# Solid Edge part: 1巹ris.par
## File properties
Author: Egon 815
Template: Normal.par
Last saved by: Egon 815
Revision: 5
Application: Solid Edge
Accuracy: 0,990
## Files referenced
..\Laev.asm
.C:\Kool\3D Modelleerimine\LaevaJoonis\Laev.asm
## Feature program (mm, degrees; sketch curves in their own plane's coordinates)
swept protrusion "unnamed SweptProtrusion 1"
sketch for "ExtrudedCutout_2" plane through (0, 0, 0) normal (0, -1, 0) x-axis (1, 0, 0)
  line (0, 7039.6525) -> (0, 4324.8507)
  line (0, 4324.8507) -> (-842.5239, 4324.8507)
  line (-842.5239, 4324.8507) -> (-842.5239, 7039.6525)
  line (-842.5239, 7039.6525) -> (0, 7039.6525)
extrude "ExtrudedCutout_2" cut finite symmetric
sketch for "unnamed Protrusion 1" plane through (11297.2682, -58110, 5032.5774) normal (-0.153386, -0.988166, 0) x-axis (0.988166, -0.153386, 0)
  line (0, 0) -> (0, 1000)
  line (0, 1000) -> (-60, 1000)
  line (-60, 1000) -> (-60, 0)
  line (0, 0) -> (-60, 0)
extrude "unnamed Protrusion 1" add to key point along +normal
sketch for "ExtrudedCutout_23" plane through (0, 0, 0) normal (1, 0, 0) x-axis (0, 1, 0)
  line (107824.8443, 5532.5774) -> (107824.8443, 5032.5774)
  line (107824.8443, 5032.5774) -> (108824.8443, 5032.5774)
  line (108824.8443, 5032.5774) -> (108824.8443, 5532.5774)
  line (108824.8443, 5532.5774) -> (107824.8443, 5532.5774)
extrude "ExtrudedCutout_23" cut finite along +normal
extrude "unnamed Cutout 1" cut finite
extrude "unnamed Cutout 2" cut finite
extrude "unnamed Cutout 3" cut finite
extrude "unnamed Cutout 4" cut finite
extrude "unnamed Cutout 5" cut finite
extrude "unnamed Cutout 6" cut finite
extrude "unnamed Cutout 7" cut finite
extrude "unnamed Cutout 8" cut finite
extrude "unnamed Cutout 9" cut finite
extrude "unnamed Cutout 10" cut finite
extrude "unnamed Cutout 11" cut finite
extrude "unnamed Cutout 12" cut finite
extrude "unnamed Cutout 13" cut finite
extrude "unnamed Cutout 14" cut finite
extrude "unnamed Cutout 15" cut finite
extrude "unnamed Cutout 16" cut finite
extrude "unnamed Cutout 17" cut finite
extrude "unnamed Cutout 18" cut finite
extrude "unnamed Cutout 19" cut finite
extrude "unnamed Cutout 20" cut finite
extrude "unnamed Cutout 21" cut finite
extrude "unnamed Cutout 22" cut finite
extrude "unnamed Cutout 23" cut finite
extrude "unnamed Cutout 24" cut finite
extrude "unnamed Cutout 25" cut finite
extrude "unnamed Cutout 26" cut finite
extrude "unnamed Cutout 27" cut finite
extrude "unnamed Cutout 28" cut finite
extrude "unnamed Cutout 29" cut finite
extrude "unnamed Cutout 30" cut finite
extrude "unnamed Cutout 31" cut finite
extrude "unnamed Cutout 32" cut finite
extrude "unnamed Cutout 33" cut finite
extrude "unnamed Cutout 34" cut finite
extrude "unnamed Cutout 35" cut finite
extrude "unnamed Cutout 36" cut finite
extrude "unnamed Cutout 37" cut finite
extrude "unnamed Cutout 38" cut finite
extrude "unnamed Cutout 39" cut finite
body pattern "unnamed BodyPattern 1"
pattern "unnamed Pattern 1"
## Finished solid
Body 1: solid body, 314 faces, 936 edges, 624 vertices.
  Faces by surface: plane 304, spline 10
  Edges by curve: line 516, intersection 256, spline 164
Bounding box of the edges (mm; curved faces can reach further): 33639.205 x 170025.692 x 1000.000, from (-16819.6027, -59033.4604, 5032.5774) to (16819.6027, 110992.2321, 6032.5774).
Planar faces by outward normal: +y 2, +z 1, -y 2, -z 149, oblique 150
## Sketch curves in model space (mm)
line (0, 108824.8443, 5032.5774) -> (0, 108824.8443, 5532.5774)
line (0, 108824.8443, 5532.5774) -> (0, 107824.8443, 5532.5774)
line (0, 107824.8443, 5532.5774) -> (0, 107824.8443, 5032.5774)
line (0, 107824.8443, 5032.5774) -> (0, 108824.8443, 5032.5774)
line (11324.5713, -58114.2381, 5532.5774) -> (11324.5713, -58114.2381, 5027.0031)
line (11324.5713, -58114.2381, 5027.0031) -> (11204.1478, -58095.5456, 5027.0031)
line (11204.1478, -58095.5456, 5027.0031) -> (11204.1478, -58095.5456, 5532.5774)
line (11204.1478, -58095.5456, 5532.5774) -> (11324.5713, -58114.2381, 5532.5774)
line (0, 0, 4324.8507) -> (-842.5239, 0, 4324.8507)
line (-842.5239, 0, 4324.8507) -> (-842.5239, 0, 7039.6525)
line (-842.5239, 0, 7039.6525) -> (0, 0, 7039.6525)
line (0, 0, 7039.6525) -> (0, 0, 4324.8507)
line (11297.2682, -58110, 6032.5774) -> (11237.9782, -58100.7968, 6032.5774)
line (11237.9782, -58100.7968, 6032.5774) -> (11237.9782, -58100.7968, 5032.5774)
line (11297.2682, -58110, 5032.5774) -> (11237.9782, -58100.7968, 5032.5774)
line (11297.2682, -58110, 5032.5774) -> (11297.2682, -58110, 6032.5774)
arc centre (246824.0429, -19203.9941, 5032.5774) radius 261036.9485 from (-11156.3293, -59033.8334, 5032.5774) through (-11227.2121, -58571.9798, 5032.5774) to (-11297.2682, -58110, 5032.5774)
arc centre (-11.4238, 110985.1557, 5032.5774) radius 13.438 from (0, 110992.2321, 5032.5774) through (0.1639, 110991.9604, 5032.5774) to (0.3213, 110991.685, 5032.5774)
arc centre (-246824.1099, -19203.9838, 5032.5774) radius 261037.0163 from (11156.3293, -59033.8334, 5032.5774) through (11227.2121, -58571.9798, 5032.5774) to (11297.2682, -58110, 5032.5774)
spline (11297.2682, 58110, 5032.5774) -> (16770.5551, -1154.4552, 5032.5774) -> (11297.2682, -58110, 5032.5774)
spline (11297.2682, 58110, 5032.5774) -> (6416.0095, 84752.182, 5032.5774) -> (0.3213, 110991.685, 5032.5774)
line (0, -44381.2454, 5032.5774) -> (0, 120116.3176, 5032.5774)
line (0, -44381.2454, 5032.5774) -> (0, -59033.8334, 5032.5774)
line (0, -59033.8334, 5032.5774) -> (0, -66244.3403, 7184.8312)
line (0, -111469.4186, 8314.9532) -> (0, -66244.3403, 7184.8312)
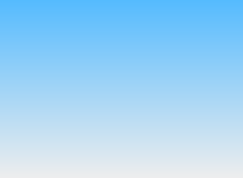
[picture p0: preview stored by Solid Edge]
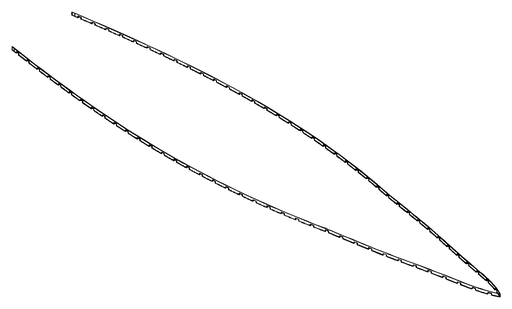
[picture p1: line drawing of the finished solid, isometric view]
